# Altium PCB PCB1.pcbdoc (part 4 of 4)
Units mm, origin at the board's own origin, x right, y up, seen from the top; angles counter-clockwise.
Board outline 94.87 x 122.94 mm, 4 copper layers (Top Layer, Inner1, Inner2, Bottom Layer); 129 components, 127 nets, 713 pads, 345 vias.
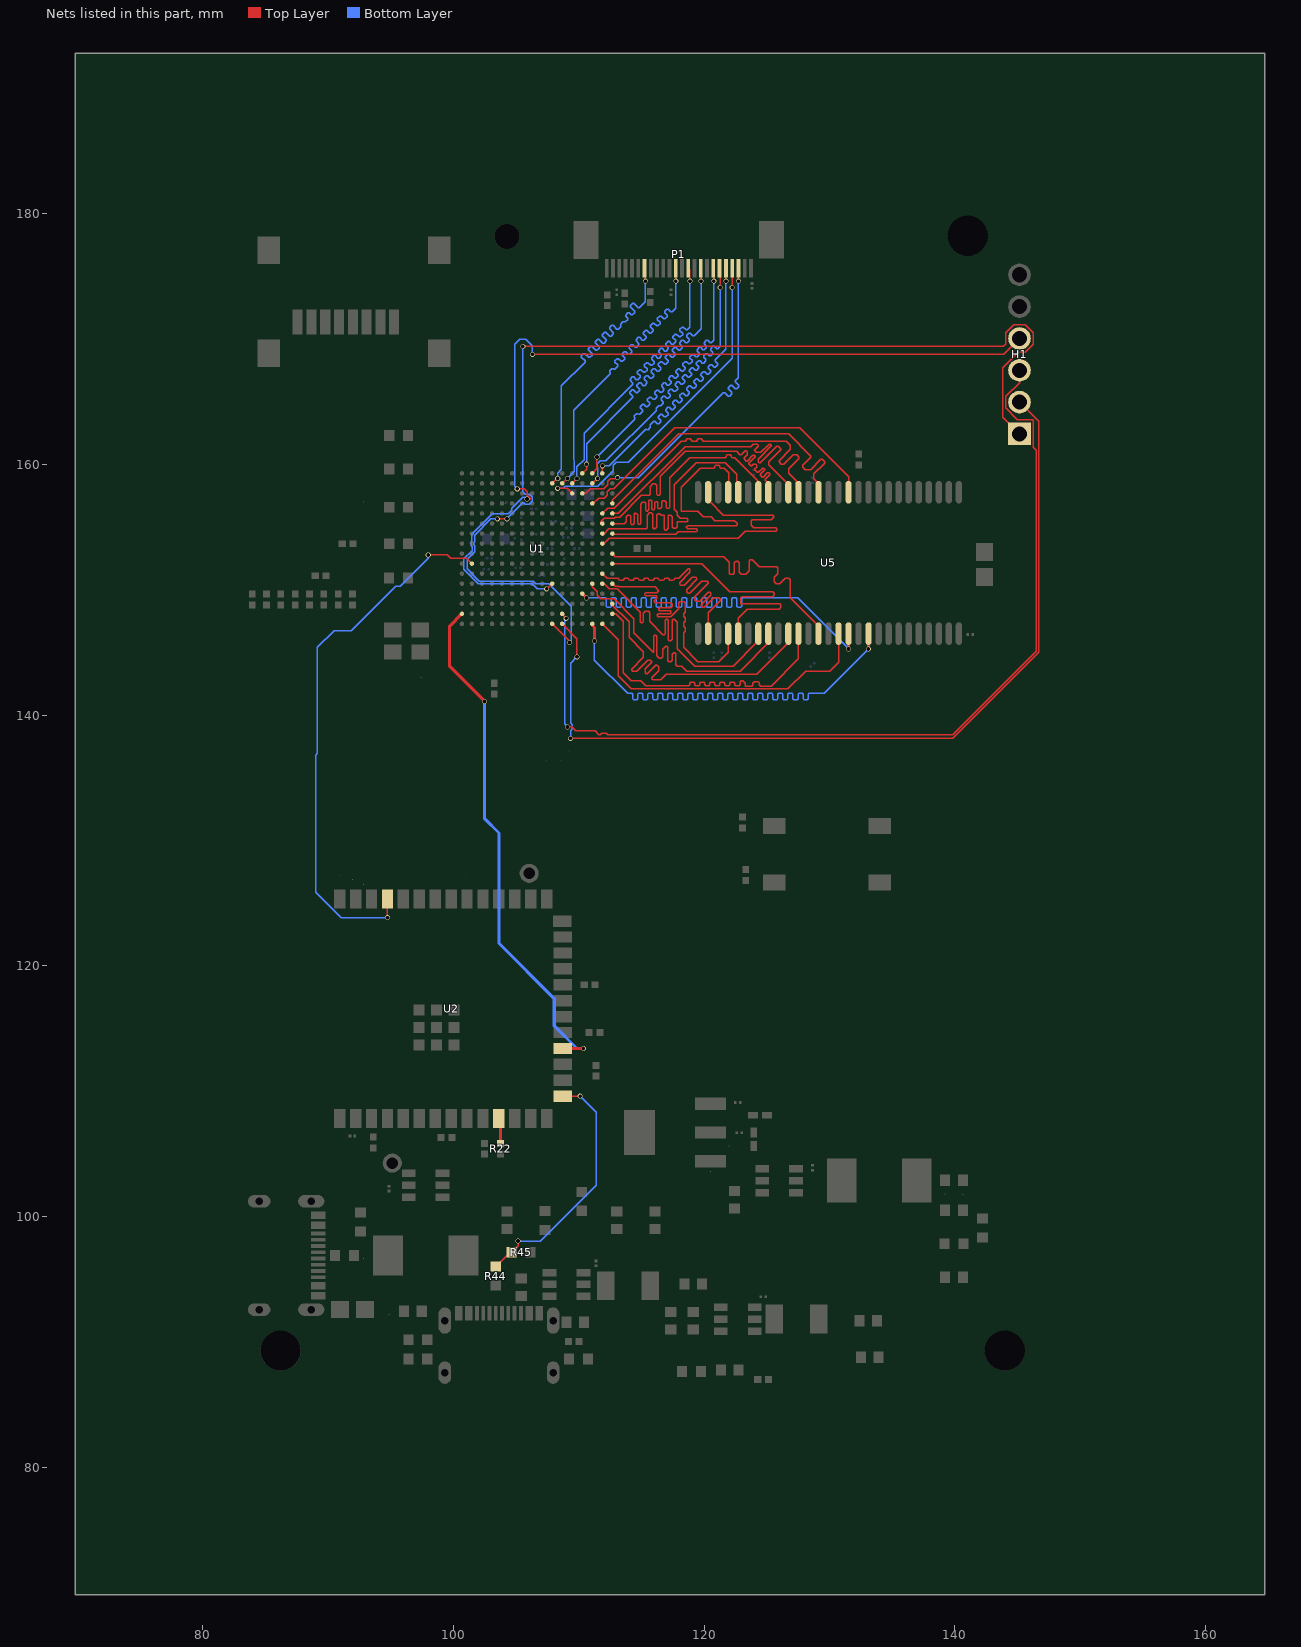
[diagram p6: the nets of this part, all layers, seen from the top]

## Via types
v1: diameter 0.4, hole 0.3, Top Layer to Bottom Layer, 308 vias
v2: diameter 1, hole 0.5, Top Layer to Bottom Layer, 35 vias
v3: diameter 0.5, hole 0.3, Top Layer to Bottom Layer, 2 vias

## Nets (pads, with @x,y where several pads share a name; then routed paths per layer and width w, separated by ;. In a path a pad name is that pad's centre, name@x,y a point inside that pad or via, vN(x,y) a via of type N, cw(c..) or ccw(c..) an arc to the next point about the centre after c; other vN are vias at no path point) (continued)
SD_DQ0: U1.L15 U5.2 | length 25
  Top Layer w0.1: U1.L15@111.88,151.289 112.262,150.907 113.129,150.907 113.2,150.836 113.2,150.82 113.27,150.749 113.529,150.749 113.6,150.82 113.6,150.836 113.67,150.907 113.929,150.907 114,150.836 114,150.82 114.07,150.749 114.329,150.749 114.4,150.82 114.4,150.836 114.47,150.907 114.729,150.907 114.8,150.836 114.8,150.82 114.87,150.749 115.129,150.749 115.2,150.82 115.2,150.836 115.27,150.907 115.529,150.907 115.6,150.836 115.6,150.82 115.67,150.749 115.929,150.749 116,150.82 116,150.836 116.07,150.907 116.329,150.907 116.4,150.836 116.4,150.82 116.47,150.749 116.729,150.749 116.8,150.82 116.8,150.836 116.87,150.907 117.129,150.907 117.2,150.836 117.2,150.82 117.27,150.749 117.529,150.749 117.6,150.82 117.6,150.836 117.67,150.907 117.97,150.907 118.731,151.667 118.843,151.667 118.872,151.638 118.872,151.384 118.049,150.561 118.049,150.429 118.11,150.368 118.411,150.368 119.046,151.003 119.355,151.003 119.426,150.932 119.426,150.832 118.618,150.024 118.618,149.86 118.745,149.733 118.836,149.733 119.795,150.693 120.25,150.693 120.321,150.622 120.321,150.528 119.253,149.46 119.253,149.225 119.38,149.098 119.634,149.098 120.34,149.804 120.452,149.804 120.523,149.733 120.523,149.581 119.761,148.819 119.761,148.717 119.888,148.59 120.015,148.59 120.777,149.352 121.175,149.352 121.295,149.231 121.295,149.131 120.321,148.157 U5.2@120.321,146.631
SD_DQ1: U1.M16 U5.4 | length 25
  Top Layer w0.1: U1.M16@112.68,150.489 112.896,150.273 113.157,150.273 113.195,150.235 116.084,150.235 116.385,149.934 116.214,149.762 115.316,149.762 115.245,149.691 115.245,149.591 115.316,149.521 116.163,149.521 116.205,149.479 116.205,149.34 116.007,149.143 116.007,149.043 116.078,148.972 117.347,148.972 117.454,148.865 117.454,148.696 117.327,148.569 116.459,148.569 116.394,148.504 116.394,148.412 116.459,148.348 117.347,148.348 117.347,148.114 117.33,148.096 116.332,148.096 116.261,148.026 116.261,147.926 116.332,147.855 117.347,147.855 117.983,148.491 117.983,148.971 118.054,149.042 118.42,149.042 118.491,148.971 118.491,148.209 118.364,148.082 118.364,147.878 118.484,147.758 118.484,147.478 118.364,147.358 118.364,147.078 118.484,146.958 118.484,146.678 118.364,146.558 118.364,145.415 119.507,144.272 121.158,144.272 121.921,145.035 U5.4@121.921,146.631
SD_DQ2: U1.K16 U5.5 | length 25.6
  Top Layer w0.1: U1.K16@112.68,152.089 119.818,152.089 122.047,149.86 125.476,149.86 125.603,149.733 125.603,149.606 125.46,149.463 123.028,149.463 122.918,149.352 122.918,148.948 122.978,148.888 126.04,148.888 126.111,148.817 126.111,148.59 125.985,148.464 123.445,148.464 122.704,147.723 122.704,146.902 122.721,146.885 U5.5@122.721,146.631
SD_DQ3: U1.M15 U5.7 | length 24.8
  Top Layer w0.1: U1.M15@111.88,150.489 111.96,150.489 111.974,150.474 112.022,150.474 112.425,150.071 113.073,150.071 114.92,148.224 114.92,147.447 114.99,147.376 115.09,147.376 115.161,147.447 115.161,148.124 115.316,148.279 115.57,148.279 115.67,148.179 115.67,147.474 116.713,146.431 116.84,146.431 116.898,146.489 116.898,147.574 116.969,147.645 117.069,147.645 117.139,147.574 117.139,146.005 117.221,145.923 117.348,145.923 117.472,146.047 117.472,147.574 117.531,147.633 117.614,147.633 117.836,147.411 117.836,145.308 119.253,143.891 122.306,143.891 124.177,145.762 124.177,146.36 124.194,146.377 124.194,146.504 U5.7@124.321,146.631
SD_DQ4: U1.M14 U5.8 | length 25.8
  Top Layer w0.1: U1.M14@111.08,150.489 111.08,150.229 111.462,149.847 111.462,149.567 111.758,149.271 112.838,149.271 114.4,147.709 114.4,146.558 115.958,145 115.99,145.032 115.99,146.304 116.061,146.375 116.161,146.375 116.231,146.304 116.231,144.727 116.432,144.526 116.586,144.526 116.705,144.645 116.705,145.267 116.923,145.486 117.023,145.486 117.094,145.415 117.094,144.372 117.194,144.272 117.348,144.272 117.44,144.364 117.44,144.86 117.558,144.978 117.658,144.978 117.729,144.907 117.729,144.04 117.856,143.913 118.196,143.913 118.599,143.51 122.87,143.51 125.278,145.918 125.278,146.474 U5.8@125.121,146.631
SD_DQ5: U1.P16 U5.10 | length 25.6
  Top Layer w0.1: U1.P16@112.68,148.889 112.68,148.78 114.025,147.435 114.025,146.198 115.159,145.064 115.159,144.61 114.229,143.681 114.229,143.581 114.3,143.51 114.62,143.51 115.509,144.399 115.697,144.399 115.824,144.272 115.824,144.206 115.303,143.686 115.303,143.37 115.374,143.3 115.474,143.3 116.199,144.024 116.368,143.855 116.368,143.533 115.817,142.982 115.817,142.882 115.888,142.811 116.522,142.811 116.967,143.256 124.198,143.256 126.721,145.779 U5.10@126.721,146.631
SD_DQ6: U1.R16 U5.11 | length 25.2
  Top Layer w0.1: U1.R16@112.68,148.089 112.944,148.089 113.538,147.495 113.538,143.383 114.169,142.752 114.931,142.752 115.332,142.351 118.774,142.351 118.844,142.422 118.844,142.55 118.915,142.621 119.174,142.621 119.244,142.55 119.244,142.422 119.315,142.351 119.574,142.351 119.644,142.422 119.644,142.55 119.715,142.621 119.974,142.621 120.044,142.55 120.044,142.422 120.115,142.351 120.374,142.351 120.444,142.422 120.444,142.55 120.515,142.621 120.774,142.621 120.844,142.55 120.844,142.422 120.915,142.351 121.174,142.351 121.244,142.422 121.244,142.55 121.315,142.621 121.574,142.621 121.644,142.55 121.644,142.422 121.715,142.351 121.974,142.351 122.044,142.422 122.044,142.55 122.115,142.621 122.374,142.621 122.444,142.55 122.444,142.422 122.515,142.351 122.792,142.351 122.892,142.451 122.892,142.677 122.963,142.748 123.063,142.748 123.269,142.542 123.269,142.291 123.781,142.291 123.881,142.391 123.881,142.55 124.008,142.677 124.333,142.677 124.404,142.607 124.404,142.421 124.504,142.321 125.335,142.321 127.508,144.494 U5.11@127.508,146.126
SD_DQ7: U1.J16 U5.13 | length 25.2
  Top Layer w0.1: U1.J16@112.68,152.889 112.915,152.654 121.567,152.654 122.003,152.217 122.003,151.315 122.074,151.244 122.315,151.244 122.415,151.344 122.415,152.146 122.552,152.282 122.673,152.282 122.811,152.144 122.811,151.409 122.976,151.244 123.304,151.244 123.587,151.527 123.587,152.289 123.698,152.4 123.841,152.4 124.409,151.832 124.413,151.836 125.786,151.836 125.857,151.765 125.857,151.266 125.603,151.012 125.603,150.638 125.746,150.495 126.043,150.495 126.478,150.931 126.746,150.931 126.875,150.801 126.875,149.367 ; 126.875,149.366 129.121,147.12 U5.13@129.121,146.631
SD_DQ8: U1.D16 U5.42 | length 25.2
  Top Layer w0.1: U1.D16@112.68,156.889 112.68,157.143 117.97,162.433 126.746,162.433 128.524,160.655 128.524,160.574 127.868,159.918 127.868,159.766 128.056,159.578 128.49,159.578 129.313,160.401 129.413,160.401 129.611,160.203 129.611,160.091 129.54,160.02 129.534,160.02 128.757,159.243 128.757,158.877 128.994,158.64 128.994,158.042 U5.42@129.121,157.915
SD_DQ9: U1.E15 U5.44 | length 25
  Top Layer w0.1: U1.E15@111.88,156.089 112.298,156.507 112.838,156.507 118.193,161.862 118.493,161.862 118.563,161.932 118.563,161.981 118.634,162.052 118.893,162.052 118.963,161.981 118.963,161.932 119.034,161.862 119.379,161.862 119.45,161.932 119.45,161.981 119.521,162.052 119.779,162.052 119.85,161.981 119.85,161.932 119.921,161.862 126.555,161.862 126.873,161.544 126.873,161.205 125.984,160.316 125.984,160.208 126.172,160.02 126.365,160.02 127.127,160.782 127.381,160.782 127.55,160.613 127.55,160.471 126.746,159.667 126.746,159.288 127.33,158.704 127.33,158.106 U5.44@127.521,157.915
SD_DQ10: U1.E16 U5.45 | length 25
  Top Layer w0.1: U1.E16@112.68,156.089 113.163,156.089 118.491,161.417 123.708,161.417 123.906,161.615 124.262,161.615 124.333,161.544 124.333,161.458 124,161.125 124.158,160.967 124.531,160.967 125.178,161.615 125.278,161.615 125.349,161.544 125.349,161.477 124.303,160.431 124.303,160.204 124.374,160.133 124.474,160.133 125.807,161.467 125.907,161.467 126.111,161.263 126.111,161.163 125.15,160.202 125.15,159.975 126.373,158.752 126.373,158.747 126.507,158.613 126.507,158.015 126.607,157.915 U5.45@126.721,157.915
SD_DQ11: U1.F15 U5.47 | length 25.1
  Top Layer w0.1: U1.F15@111.88,155.289 111.753,155.416 111.753,155.441 112.019,155.707 112.838,155.707 112.929,155.798 113.253,155.798 114.991,157.536 115.626,157.536 115.697,157.607 115.697,158.242 115.9,158.445 116.105,158.445 116.205,158.345 116.205,157.607 116.276,157.536 116.425,157.536 116.496,157.607 116.496,159.041 118.491,161.036 122.598,161.036 122.858,160.776 122.943,160.776 123.273,161.107 123.373,161.107 123.444,161.036 123.444,160.782 123.19,160.528 123.19,160.444 123.376,160.259 123.429,160.259 123.896,160.726 124.008,160.726 124.079,160.655 124.079,160.61 123.571,160.102 123.571,160.063 123.771,159.864 123.927,160.02 124.143,160.02 124.206,159.957 124.206,159.797 124.048,159.639 124.048,159.586 124.249,159.385 124.333,159.385 124.658,159.71 124.77,159.71 124.841,159.639 124.841,159.59 124.46,159.209 124.46,159.174 124.655,158.979 124.702,158.979 125.051,159.329 125.151,159.329 125.222,159.258 125.222,159.16 124.884,158.822 124.884,158.75 125.121,158.513 U5.47@125.121,157.915
SD_DQ12: U1.F16 U5.48 | length 25.1
  Top Layer w0.1: U1.F16@112.68,155.289 113.633,155.289 113.792,155.448 113.792,155.829 113.919,155.956 114.086,155.956 114.129,155.912 114.129,155.265 114.2,155.194 114.3,155.194 114.408,155.302 114.408,156.064 114.466,156.122 114.554,156.122 114.689,155.987 114.689,155.325 114.764,155.25 114.864,155.25 114.935,155.321 114.935,156.845 115.062,156.972 115.248,156.972 115.329,156.892 115.329,156.337 115.399,156.266 115.468,156.266 115.57,156.369 115.57,157.094 115.633,157.157 115.766,157.157 115.837,157.086 115.837,156.464 115.907,156.393 116.007,156.393 116.078,156.464 116.078,156.972 116.142,157.036 116.268,157.036 116.303,157.001 116.303,156.52 116.374,156.449 116.474,156.449 116.615,156.591 116.615,157.001 116.713,157.099 116.84,157.099 116.967,156.972 116.967,156.591 117.038,156.52 117.206,156.52 117.277,156.591 117.277,158.933 118.872,160.528 121.681,160.528 121.751,160.599 121.751,160.711 121.822,160.782 122.081,160.782 122.151,160.711 122.151,160.599 122.222,160.528 122.428,160.528 124.263,158.693 124.263,158.015 124.321,157.957 U5.48@124.321,157.915
SD_DQ13: U1.G15 U5.50 | length 25.1
  Top Layer w0.1: U1.G15@111.88,154.489 112.021,154.489 112.403,154.871 115.374,154.871 115.443,154.94 115.443,155.956 115.626,156.139 115.768,156.139 115.895,156.012 115.895,154.94 115.965,154.869 116.065,154.869 116.205,155.009 116.205,155.956 116.332,156.083 116.459,156.083 116.586,155.956 116.802,155.956 116.802,154.813 116.873,154.742 116.973,154.742 117.132,154.902 117.132,155.899 117.189,155.956 117.348,155.956 117.475,155.829 117.475,155.013 117.575,154.913 117.756,154.913 117.856,155.013 117.856,155.406 117.898,155.448 118.618,155.448 118.689,155.519 118.689,155.619 118.61,155.697 118.115,155.697 117.856,155.956 117.856,156.197 117.614,156.44 117.614,158.387 119.374,160.147 121.666,160.147 122.603,159.21 122.603,158.034 U5.50@122.721,157.915
SD_DQ14: U1.G16 U5.51 | length 25
  Top Layer w0.1: U1.G16@112.68,154.489 112.743,154.425 117.722,154.425 117.916,154.619 119.38,154.619 119.451,154.69 119.451,154.79 119.38,154.86 118.698,154.86 118.585,154.973 118.585,155.034 118.68,155.129 122.555,155.129 122.626,155.199 122.626,155.299 122.406,155.519 120.86,155.519 120.55,155.829 119.926,155.829 119.507,156.248 118.157,156.248 118.157,158.162 119.697,159.702 120.761,159.702 120.832,159.773 120.832,159.847 120.902,159.918 121.161,159.918 121.232,159.847 121.232,159.773 121.303,159.702 121.602,159.702 121.967,159.338 121.967,158.25 U5.51@121.985,158.233
SD_DQ15: U1.H15 U5.53 | length 25.3
  Top Layer w0.1: U1.H15@111.88,153.689 112.007,153.689 112.425,154.107 122.711,154.107 123.268,154.664 125.696,154.664 125.801,154.769 125.801,154.869 125.73,154.94 123.952,154.94 123.754,155.138 123.754,155.504 123.825,155.575 125.336,155.575 125.547,155.785 125.547,155.885 125.476,155.956 121.539,155.956 120.448,157.047 U5.53@120.448,157.788
SD_DQM0: U1.T15 U5.15 | length 25.8
  Top Layer w0.1: U1.T15@111.88,147.289 113.157,146.012 113.157,143.129 114.195,142.091 126.69,142.091 128.109,143.51 130.008,143.51 130.721,144.223 U5.15@130.721,146.504
SD_DQM1: U1.D14 U5.39 | length 25.9
  Top Layer w0.1: U1.D14@111.08,156.889 111.169,156.889 111.587,157.307 112.038,157.307 112.262,157.531 112.262,157.811 112.522,158.071 112.802,158.071 117.672,162.941 127.619,162.941 131.53,159.031 131.53,158.042 U5.39@131.403,157.915
SD_RAS_N: U1.T14 U5.18 | length 43.8
  Top Layer w0.254: U1.T14@111.125,147.123 111.252,146.996 v1(111.252,145.923) ; v1(133.096,145.288) 133.121,145.313 U5.18@133.121,146.504
  Bottom Layer w0.1: v1(111.252,145.923) 111.252,144.399 113.919,141.732 114.219,141.732 114.29,141.661 114.29,141.295 114.36,141.224 114.619,141.224 114.69,141.295 114.69,141.661 114.76,141.732 115.019,141.732 115.09,141.661 115.09,141.295 115.16,141.224 115.419,141.224 115.49,141.295 115.49,141.661 115.56,141.732 115.819,141.732 115.89,141.661 115.89,141.295 115.96,141.224 116.219,141.224 116.29,141.295 116.29,141.661 116.36,141.732 116.619,141.732 116.69,141.661 116.69,141.295 116.76,141.224 117.019,141.224 117.09,141.295 117.09,141.661 117.16,141.732 117.419,141.732 117.49,141.661 117.49,141.295 117.56,141.224 117.819,141.224 117.89,141.295 117.89,141.661 117.96,141.732 118.219,141.732 118.29,141.661 118.29,141.295 118.36,141.224 118.619,141.224 118.69,141.295 118.69,141.661 118.76,141.732 119.019,141.732 119.09,141.661 119.09,141.295 119.16,141.224 119.419,141.224 119.49,141.295 119.49,141.661 119.56,141.732 119.819,141.732 119.89,141.661 119.89,141.295 119.96,141.224 120.219,141.224 120.29,141.295 120.29,141.661 120.36,141.732 120.619,141.732 120.69,141.661 120.69,141.295 120.76,141.224 121.019,141.224 121.09,141.295 121.09,141.661 121.16,141.732 121.419,141.732 121.49,141.661 121.49,141.295 121.56,141.224 121.819,141.224 121.89,141.295 121.89,141.661 121.96,141.732 122.219,141.732 122.29,141.661 122.29,141.295 122.36,141.224 122.619,141.224 122.69,141.295 122.69,141.661 122.76,141.732 123.019,141.732 123.09,141.661 123.09,141.295 123.16,141.224 123.419,141.224 123.49,141.295 123.49,141.661 123.56,141.732 123.819,141.732 123.89,141.661 123.89,141.295 123.96,141.224 124.219,141.224 124.29,141.295 124.29,141.661 124.36,141.732 124.619,141.732 124.69,141.661 124.69,141.295 124.76,141.224 125.019,141.224 125.09,141.295 125.09,141.661 125.16,141.732 125.419,141.732 125.49,141.661 125.49,141.295 125.56,141.224 125.819,141.224 125.89,141.295 125.89,141.661 125.96,141.732 126.219,141.732 126.29,141.661 126.29,141.295 126.36,141.224 126.619,141.224 126.69,141.295 126.69,141.661 126.76,141.732 127.019,141.732 127.09,141.661 127.09,141.295 127.16,141.224 127.419,141.224 127.49,141.295 127.49,141.661 127.56,141.732 127.819,141.732 127.89,141.661 127.89,141.295 127.96,141.224 128.219,141.224 128.29,141.295 128.29,141.661 128.36,141.732 129.588,141.732 133.096,145.24 v1(133.096,145.288)
SD_WE_N: U1.N13 U5.16 | length 43.3
  Top Layer w0.254: U1.N13@110.28,149.689 v1(110.617,149.352) ; v1(131.521,145.288) U5.16@131.521,146.504
  Bottom Layer w0.1: v1(110.617,149.352) 112.125,149.352 112.196,149.281 112.196,148.661 112.267,148.59 112.525,148.59 112.596,148.661 112.596,149.281 112.667,149.352 112.925,149.352 112.996,149.281 112.996,148.661 113.067,148.59 113.325,148.59 113.396,148.661 113.396,149.281 113.467,149.352 113.725,149.352 113.796,149.281 113.796,148.661 113.867,148.59 114.125,148.59 114.196,148.661 114.196,149.281 114.267,149.352 114.525,149.352 114.596,149.281 114.596,148.661 114.667,148.59 114.925,148.59 114.996,148.661 114.996,149.281 115.067,149.352 115.325,149.352 115.396,149.281 115.396,148.661 115.467,148.59 115.725,148.59 115.796,148.661 115.796,149.281 115.867,149.352 116.125,149.352 116.196,149.281 116.196,148.661 116.267,148.59 116.525,148.59 116.596,148.661 116.596,149.281 116.667,149.352 116.925,149.352 116.996,149.281 116.996,148.661 117.067,148.59 117.325,148.59 117.396,148.661 117.396,149.281 117.467,149.352 117.725,149.352 117.796,149.281 117.796,148.661 117.867,148.59 118.125,148.59 118.196,148.661 118.196,149.281 118.267,149.352 118.525,149.352 118.596,149.281 118.596,148.661 118.667,148.59 118.925,148.59 118.996,148.661 118.996,149.281 119.067,149.352 119.325,149.352 119.396,149.281 119.396,148.661 119.467,148.59 119.725,148.59 119.796,148.661 119.796,149.281 119.867,149.352 120.125,149.352 120.196,149.281 120.196,148.661 120.267,148.59 120.525,148.59 120.596,148.661 120.596,149.281 120.667,149.352 120.925,149.352 120.996,149.281 120.996,148.661 121.067,148.59 121.325,148.59 121.396,148.661 121.396,149.281 121.467,149.352 121.725,149.352 121.796,149.281 121.796,148.661 121.867,148.59 122.125,148.59 122.196,148.661 122.196,149.281 122.267,149.352 122.525,149.352 122.596,149.281 122.596,148.661 122.667,148.59 122.925,148.59 122.996,148.661 122.996,149.281 123.067,149.352 127.457,149.352 v1(131.521,145.288)
SDA: R22.1 U2.11 | length 1.9
  Top Layer w0.254: R22.1@103.754,105.918 U2.11@103.754,107.836
SSPI_CS_N: U1.R1 U2.18 | length 41.3
  Top Layer w0.254: U1.R1@100.68,148.089 99.695,147.104 99.695,143.891 v1(102.489,141.097) ; U2.18@108.844,113.411 v1(110.363,113.411)
  Bottom Layer w0.254: v1(102.489,141.097) 102.489,131.743 103.632,130.6 103.632,121.793 108.05,117.375 108.05,115.216 109.855,113.411 v1(110.363,113.411)
TCK: H1.1 U1.T10 | length 88.4
  Top Layer w0.1: v1(103.501,155.661) 103.712,155.661 103.722,155.671 104.038,155.671 104.048,155.661 104.226,155.661 v1@104.267,155.702 ; v1(105.537,169.418) 143.875,169.418 144.059,169.602 144.059,170.509 144.705,171.155 145.617,171.155 146.263,170.509 146.263,169.597 145.617,168.951 145.041,168.951 143.808,167.719 143.808,163.786 H1.1@145.161,162.433 ; U1.T10@107.88,147.289 109.264,145.905 v1(109.264,145.796)
  Bottom Layer w0.1: v1(103.501,155.661) 102.985,155.661 101.682,154.358 101.682,153.802 101.633,153.752 101.633,153.6 101.694,153.538 101.694,153.04 101.092,152.438 101.092,151.667 102.064,150.695 106.363,150.695 106.576,150.481 107.609,150.481 109.395,148.695 109.395,145.927 v1(109.264,145.796) ; v1(104.267,155.661) 105.537,156.931 105.622,156.931 105.714,156.839 106.047,156.839 106.282,157.075 106.282,157.408 106.047,157.643 105.714,157.643 105.537,157.82 v1(105.537,169.418)
TDI: H1.3 U1.R11 | length 74.5
  Top Layer w0.1: U1.R11@108.68,148.089 108.68,148.041 v1(108.993,147.728) ; v1(109.093,139.065) 109.421,139.065 109.748,138.738 111.298,138.738 111.606,138.43 111.72,138.43 111.847,138.557 112.181,138.557 112.308,138.43 139.827,138.43 146.485,145.088 146.485,161.153 146.272,161.366 146.272,163.579 144.996,163.579 144.059,164.517 144.059,165.429 145.161,166.531 H1.3@145.161,167.513
  Bottom Layer w0.1: v1(108.993,147.728) 108.862,147.597 108.862,139.296 v1(109.093,139.065)
TDO: H1.4 U1.M10 | length 72.1
  Top Layer w0.1: v1(105.092,158.054) 105.304,158.054 105.322,158.071 105.638,158.071 105.898,157.811 105.898,157.531 106.122,157.307 106.122,157.271 106.092,157.241 v1(105.88,157.241) ; v1(106.299,168.783) 143.891,168.783 H1.4@145.161,170.053 ; v1(107.442,150.079) 107.47,150.079 U1.M10@107.88,150.489
  Bottom Layer w0.1: v1(105.092,158.054) 104.881,158.265 104.881,169.601 105.281,170.001 105.762,170.001 106.299,169.464 v1(106.299,168.783) ; v1(105.88,157.241) 105.753,157.368 105.524,157.368 104.669,156.514 104.669,156.357 104.375,156.063 103.104,156.063 101.482,154.441 101.482,153.884 101.433,153.835 101.433,153.517 101.494,153.456 101.494,153.122 100.838,152.466 100.838,151.638 101.981,150.495 106.28,150.495 106.695,150.079 v1(107.442,150.079)
TMS: H1.2 U1.T11 | length 70.7
  Top Layer w0.1: U1.T11@108.68,147.289 109.855,146.114 v1(109.855,144.653) ; v1(109.347,138.155) 139.835,138.155 146.685,145.005 146.685,163.449 H1.2@145.161,164.973
  Bottom Layer w0.1: v1(109.347,138.155) 109.347,138.75 109.495,138.898 109.495,139.232 109.347,139.38 109.347,144.145 v1(109.855,144.653)
TX: U1.K2 U2.37 | length 43.6
  Top Layer w0.1: v1@94.737,123.825 U2.37@94.737,125.336 ; v1@97.917,152.781 99.507,152.781 99.782,152.506 101.061,152.506 ; 101.062,152.507 U1.K2@101.48,152.089
  Bottom Layer w0.1: v1(94.737,123.846) 91.038,123.846 89.004,125.88 89.004,136.809 89.154,136.959 89.154,145.415 90.478,146.739 91.85,146.739 95.385,150.274 95.753,150.274 97.992,152.513 v1(97.992,152.781)
USB_VBUS: R44.1 R45.2 U2.15 | length 19.9
  Top Layer w0.1: R44.1@103.378,96.003 104.53,97.155 R45.2@104.657,97.155 105.156,97.654 v1(105.156,98.044) ; U2.15@108.717,109.601 v1(110.109,109.601)
  Bottom Layer w0.1: v1(105.156,98.044) 106.934,98.044 111.379,102.489 111.379,108.331 v1(110.109,109.601)
VSYNC: P1.7 U1.B10 | length 27.1
  Top Layer w0.1: U1.B10@107.88,158.489 108.276,158.885 v1(108.323,158.885) ; P1.7@115.237,175.655 115.316,175.577 v1(115.316,174.625)
  Bottom Layer w0.1: v1(108.323,158.885) 108.323,159.317 108.606,159.599 108.606,166.264 110.501,168.159 110.501,168.259 110.192,168.568 110.192,168.668 110.375,168.851 110.475,168.851 110.784,168.542 110.884,168.542 111.067,168.725 111.067,168.825 110.758,169.134 110.758,169.234 110.94,169.417 111.04,169.417 111.35,169.108 111.45,169.108 111.632,169.29 111.632,169.39 111.323,169.7 111.323,169.8 111.506,169.982 111.606,169.982 111.915,169.673 112.015,169.673 112.198,169.856 112.198,169.956 111.889,170.265 111.889,170.365 112.072,170.548 112.172,170.548 112.481,170.239 112.581,170.239 112.764,170.422 112.764,170.522 112.455,170.831 112.455,170.931 112.638,171.114 112.738,171.114 113.047,170.805 113.147,170.805 113.333,170.991 113.333,171.184 113.52,171.37 113.712,171.37 113.895,171.553 113.895,171.653 113.729,171.819 113.729,171.919 113.912,172.102 114.012,172.102 114.178,171.936 114.278,171.936 114.461,172.119 114.461,172.219 114.116,172.563 114.116,172.663 114.299,172.846 114.399,172.846 114.744,172.502 114.844,172.502 115.316,172.974 v1(115.316,174.625)
Y2: P1.19 U1.B14 | length 27
  Top Layer w0.1: U1.B14@111.08,158.489 111.468,158.877 v1(111.506,158.877) ; P1.19@121.237,175.655 121.285,175.607 v1(121.285,174.117)
  Bottom Layer w0.1: v1(111.506,158.877) 111.506,159.705 111.485,159.726 111.485,160.06 111.72,160.295 112.162,160.295 116.166,164.299 116.166,164.465 116.367,164.665 116.532,164.665 116.748,164.881 116.748,164.981 116.56,165.169 116.56,165.269 116.742,165.451 116.842,165.451 117.03,165.263 117.13,165.263 117.313,165.446 117.313,165.546 117.125,165.734 117.125,165.834 117.308,166.017 117.408,166.017 117.596,165.829 117.696,165.829 117.879,166.012 117.879,166.112 117.691,166.3 117.691,166.4 117.874,166.583 117.974,166.583 118.162,166.395 118.262,166.395 118.445,166.578 118.445,166.678 118.257,166.866 118.257,166.966 118.44,167.148 118.54,167.148 118.728,166.961 118.828,166.961 119.01,167.143 119.01,167.243 118.822,167.431 118.822,167.531 119.005,167.714 119.105,167.714 119.293,167.526 119.393,167.526 119.576,167.709 119.576,167.809 119.388,167.997 119.388,168.097 119.571,168.28 119.671,168.28 119.859,168.092 119.959,168.092 120.142,168.275 120.142,168.375 119.954,168.563 119.954,168.663 120.137,168.846 120.237,168.846 120.425,168.658 120.525,168.658 120.707,168.84 120.707,168.94 120.519,169.128 120.519,169.228 120.702,169.411 120.802,169.411 120.99,169.223 121.09,169.223 121.285,169.418 v1(121.285,174.117)
Y3: P1.21 U1.C12 | length 27
  Top Layer w0.1: v1(108.317,158.1) 109.069,158.1 U1.C12@109.48,157.689 ; v1(122.239,174.117) P1.21@122.239,175.652
  Bottom Layer w0.1: v1(108.317,158.1) 108.766,158.1 108.925,158.259 111.523,158.259 112.755,159.491 112.755,159.933 112.99,160.168 113.94,160.168 122.239,168.467 v1(122.239,174.117)
Y4: P1.22 U1.C13 | length 27
  Top Layer w0.1: U1.C13@110.28,157.689 110.54,157.689 110.922,158.071 112.002,158.071 112.298,158.367 112.298,158.647 112.522,158.871 113.014,158.871 v1(113.089,158.945) ; v1(122.739,174.625) P1.22@122.739,175.652
  Bottom Layer w0.1: v1(113.089,158.945) 114.749,158.945 121.544,165.74 121.644,165.74 121.925,165.459 122.025,165.459 122.208,165.642 122.208,165.742 121.927,166.023 121.927,166.123 122.11,166.306 122.21,166.306 122.491,166.025 122.591,166.025 122.774,166.208 122.774,166.308 122.493,166.589 122.493,166.689 122.739,166.935 v1(122.739,174.625)
Y5: P1.20 U1.A15 | length 27
  Top Layer w0.1: U1.A15@111.88,159.289 111.887,159.296 v1(111.887,159.893) ; v1(121.739,174.625) P1.20@121.739,175.652
  Bottom Layer w0.1: v1(111.887,159.893) 112.433,159.893 115.33,162.791 115.43,162.791 115.438,162.782 115.538,162.782 115.721,162.965 115.721,163.065 115.713,163.074 115.713,163.174 115.973,163.434 116.073,163.434 116.272,163.235 116.372,163.235 116.555,163.418 116.555,163.518 116.356,163.717 116.356,163.817 116.539,163.999 116.639,163.999 116.838,163.801 116.938,163.801 117.121,163.984 117.121,164.084 116.922,164.282 116.922,164.382 117.105,164.565 117.205,164.565 117.403,164.366 117.503,164.366 117.686,164.549 117.686,164.649 117.488,164.848 117.488,164.948 117.67,165.131 117.77,165.131 117.969,164.932 118.069,164.932 118.252,165.115 118.252,165.215 118.053,165.414 118.053,165.514 118.236,165.696 118.336,165.696 118.535,165.498 118.635,165.498 118.818,165.681 118.818,165.781 118.619,165.979 118.619,166.079 118.802,166.262 118.902,166.262 119.1,166.063 119.2,166.063 119.383,166.246 119.383,166.346 119.185,166.545 119.185,166.645 119.367,166.828 119.467,166.828 119.666,166.629 119.766,166.629 119.949,166.812 119.949,166.912 119.75,167.111 119.75,167.211 119.933,167.393 120.033,167.393 120.232,167.195 120.332,167.195 120.515,167.378 120.515,167.478 120.316,167.676 120.316,167.776 120.499,167.959 120.599,167.959 120.797,167.76 120.897,167.76 121.08,167.943 121.08,168.043 120.882,168.242 120.882,168.342 121.739,169.199 v1(121.739,174.625)
Y6: P1.18 U1.A14 | length 27.1
  Top Layer w0.1: U1.A14@111.08,159.289 111.445,159.654 v1(111.445,160.589) ; P1.18@120.737,175.655 120.777,175.615 v1(120.777,174.625)
  Bottom Layer w0.1: v1(111.445,160.589) 114.484,163.627 114.484,163.727 114.438,163.772 114.438,163.872 114.621,164.055 114.721,164.055 114.767,164.01 114.867,164.01 115.096,164.239 115.096,164.339 114.91,164.524 114.91,164.624 115.093,164.807 115.193,164.807 115.378,164.621 115.478,164.621 115.661,164.804 115.661,164.904 115.476,165.09 115.476,165.19 115.659,165.372 115.759,165.372 115.944,165.187 116.044,165.187 116.227,165.37 116.227,165.47 116.042,165.655 116.042,165.755 116.224,165.938 116.324,165.938 116.51,165.753 116.61,165.753 116.793,165.936 116.793,166.036 116.607,166.221 116.607,166.321 116.79,166.504 116.89,166.504 117.075,166.318 117.175,166.318 117.358,166.501 117.358,166.601 117.173,166.787 117.173,166.887 117.356,167.07 117.456,167.07 117.641,166.884 117.741,166.884 117.924,167.067 117.924,167.167 117.739,167.352 117.739,167.452 117.921,167.635 118.021,167.635 118.207,167.45 118.307,167.45 118.49,167.633 118.49,167.733 118.304,167.918 118.304,168.018 118.487,168.201 118.587,168.201 118.772,168.016 118.872,168.016 119.055,168.198 119.055,168.298 118.87,168.484 118.87,168.584 119.053,168.767 119.153,168.767 119.338,168.581 119.438,168.581 119.621,168.764 119.621,168.864 119.436,169.049 119.436,169.149 119.619,169.332 119.719,169.332 119.904,169.147 120.004,169.147 120.187,169.33 120.187,169.43 120.001,169.615 120.001,169.715 120.184,169.898 120.284,169.898 120.47,169.713 120.57,169.713 120.777,169.92 v1(120.777,174.625)
Y7: P1.16 U1.A13 | length 26.9
  Top Layer w0.1: U1.A13@110.28,159.289 110.617,159.626 v1(110.617,160.02) ; P1.16@119.737,175.654 119.761,175.63 v1(119.761,174.625)
  Bottom Layer w0.1: v1(110.617,160.02) 110.617,161.671 114.295,165.349 114.295,165.449 114.078,165.667 114.078,165.767 114.26,165.949 114.36,165.949 114.578,165.732 114.678,165.732 114.861,165.915 114.861,166.015 114.643,166.232 114.643,166.332 114.826,166.515 114.926,166.515 115.144,166.298 115.244,166.298 115.426,166.48 115.426,166.58 115.209,166.798 115.209,166.898 115.392,167.081 115.492,167.081 115.709,166.863 115.809,166.863 115.992,167.046 115.992,167.146 115.775,167.364 115.775,167.464 115.957,167.646 116.057,167.646 116.275,167.429 116.375,167.429 116.558,167.612 116.558,167.712 116.34,167.929 116.34,168.029 116.523,168.212 116.623,168.212 116.841,167.995 116.941,167.995 117.123,168.177 117.123,168.277 116.906,168.495 116.906,168.595 117.089,168.778 117.189,168.778 117.406,168.56 117.506,168.56 117.689,168.743 117.689,168.843 117.472,169.061 117.472,169.161 117.654,169.343 117.754,169.343 117.972,169.126 118.072,169.126 118.255,169.309 118.255,169.409 118.037,169.626 118.037,169.726 118.22,169.909 118.32,169.909 118.538,169.692 118.638,169.692 118.82,169.874 118.82,169.974 118.603,170.192 118.603,170.292 118.786,170.475 118.886,170.475 119.103,170.257 119.203,170.257 119.761,170.815 v1(119.761,174.625)
Y8: P1.14 U1.B12 | length 27
  Top Layer w0.1: U1.B12@109.48,158.489 109.855,158.864 v1(109.855,158.877) ; P1.14@118.738,175.655 118.868,175.524 v1(118.868,174.621)
  Bottom Layer w0.1: v1(109.855,158.877) 109.855,159.827 110.417,160.389 110.417,162.487 114.315,166.385 114.315,166.485 114.097,166.702 114.097,166.802 114.28,166.985 114.38,166.985 114.598,166.768 114.698,166.768 114.891,166.961 114.891,167.061 114.674,167.279 114.674,167.379 114.857,167.562 114.957,167.562 115.174,167.344 115.274,167.344 115.457,167.527 115.457,167.627 115.239,167.844 115.239,167.944 115.422,168.127 115.522,168.127 115.74,167.91 115.84,167.91 116.023,168.093 116.023,168.193 115.805,168.41 115.805,168.51 115.988,168.693 116.088,168.693 116.305,168.475 116.405,168.475 116.588,168.658 116.588,168.758 116.371,168.976 116.371,169.076 116.554,169.259 116.654,169.259 116.871,169.041 116.971,169.041 117.154,169.224 117.154,169.324 116.936,169.541 116.936,169.641 117.119,169.824 117.219,169.824 117.437,169.607 117.537,169.607 117.72,169.79 117.72,169.89 117.502,170.107 117.502,170.207 117.685,170.39 117.785,170.39 118.003,170.173 118.103,170.173 118.285,170.355 118.285,170.455 118.068,170.673 118.068,170.773 118.251,170.956 118.351,170.956 118.568,170.738 118.668,170.738 118.868,170.938 v1(118.868,174.621)
Y9: P1.12 U1.B11 | length 27
  Top Layer w0.1: U1.B11@108.68,158.489 109.068,158.877 v1(109.093,158.877) ; v1(117.738,174.625) P1.12@117.738,175.655
  Bottom Layer w0.1: v1(109.093,158.877) 109.655,159.439 109.655,160.286 109.58,160.361 109.58,164.317 112.492,167.229 112.492,167.329 112.465,167.356 112.465,167.456 112.648,167.639 112.748,167.639 112.775,167.612 112.875,167.612 113.101,167.838 113.101,167.938 112.884,168.156 112.884,168.256 113.067,168.439 113.167,168.439 113.384,168.221 113.484,168.221 113.667,168.404 113.667,168.504 113.449,168.721 113.449,168.821 113.632,169.004 113.732,169.004 113.95,168.787 114.05,168.787 114.233,168.97 114.233,169.07 114.015,169.287 114.015,169.387 114.198,169.57 114.298,169.57 114.516,169.353 114.616,169.353 114.798,169.535 114.798,169.635 114.581,169.853 114.581,169.953 114.764,170.136 114.864,170.136 115.081,169.918 115.181,169.918 115.364,170.101 115.364,170.201 115.147,170.419 115.147,170.519 115.329,170.701 115.429,170.701 115.647,170.484 115.747,170.484 115.93,170.667 115.93,170.767 115.712,170.984 115.712,171.084 115.895,171.267 115.995,171.267 116.213,171.05 116.313,171.05 116.495,171.232 116.495,171.332 116.278,171.55 116.278,171.65 116.461,171.833 116.561,171.833 116.778,171.615 116.878,171.615 117.061,171.798 117.061,171.898 116.844,172.116 116.844,172.216 117.026,172.398 117.126,172.398 117.344,172.181 117.444,172.181 117.738,172.475 v1(117.738,174.625)
pads on no net: P1.1 P1.10 SCREW1.1 SCREW2.1 SCREW3.1 SCREW4.1 U1.A9 U1.B3 U1.B8 U1.B13 U1.B15 U1.B16 U1.C1 U1.C2 U1.C3 U1.C4 U1.C5 U1.C6 U1.C9 U1.C10 U1.C11 U1.C14 U1.C15 U1.C16 U1.D1 U1.D3 U1.D4 U1.D5 U1.D6 U1.D7 U1.D8 U1.D9 U1.D10 U1.D11 U1.D12 U1.D13 U1.E3 U1.E4 U1.E5 U1.E6 U1.E7 U1.E8 U1.E9 U1.E10 U1.E11 U1.E12 U1.E13 U1.E14 U1.F3 U1.F4 U1.F5 U1.F12 U1.F13 U1.F14 U1.G3 U1.G4 U1.G5 U1.G12 U1.G13 U1.G14 U1.H2 U1.H3 U1.H4 U1.H5 U1.H12 U1.H13 U1.H14 U1.J3 U1.J4 U1.J5 U1.J12 U1.J13 U1.K3 U1.K4 U1.K5 U1.K13 U1.K14 U1.K15 U1.L1 U1.L2 U1.L3 U1.L4 U1.L5 U1.L13 U1.L14 U1.L16 U1.M2 U1.M3 U1.M4 U1.M5 U1.M6 U1.M7 U1.M9 U1.M11 U1.M12 U1.M13 U1.N1 U1.N3 U1.N4 U1.N5 U1.N6 U1.N7 U1.N8 U1.N9 U1.N11 U1.N12 U1.N14 U1.N16 U1.P1 U1.P2 U1.P3 U1.P4 U1.P5 U1.P6 U1.P7 U1.P8 U1.P11 U1.P12 U1.P13 U1.P14 U1.P15 U1.R2 U1.R3 U1.R4 U1.R5 U1.R6 U1.R7 U1.R8 U1.R12 U1.R14 U1.T13 U2.4 U2.16 U2.26 U2.28 U2.29 U2.30 U2.32 U2.33 U2.34 U2.35 U2.38 U2.39 U5.40 U8.4 USB1.A6 USB1.A7 USB1.A8 USB1.B6 USB1.B7 USB1.B8 USB2.A8 USB2.B6 USB2.B7 USB2.B8
copper on no net: | length 14.9
  Top Layer w0.1: 91.948,126.873 92.197,126.624 92.197,125.336 ; 92.837,126.492 93.467,125.862 93.467,125.336 ; 94.737,107.836 94.966,107.607 v1(94.966,106.202) ; 103.627,125.336 103.627,125.971 105.164,127.508 105.791,127.508 106.045,127.254 ; v1(108.332,148.589) 108.381,148.59 108.68,148.889
  Top Layer w0.254: v1(99.822,148.921) 100.648,148.921 100.68,148.889 ; v1(101.077,149.334) 101.48,148.93 101.48,148.889 ; v1(101.875,149.246) 101.875,149.284 102.28,149.689 ; v1(102.632,148.489) 102.68,148.489 103.08,148.889 ; v1(102.743,149.352) 103.08,149.689
  Bottom Layer w0.1: v1(94.966,106.202) 95.123,106.045 95.123,104.267 ; v1(108.332,148.589) 108.712,148.209 108.712,148.082

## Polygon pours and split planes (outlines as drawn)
+3V3 on Inner2 (solid, remove dead copper): 76.2,185.674 158.369,185.674 158.369,76.2 76.2,76.2
GND on Inner1 (solid, remove dead copper): 77.724,186.436 152.781,186.436 152.781,82.296 77.724,82.296

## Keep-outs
Board Outline Layer:
  lines w0.254: 83.058,86.229 147.058,86.229 147.058,181.229 83.058,181.229 83.058,86.229

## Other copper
Top Layer:
  drawing of 759 lines, arcs and shapes, not listed
Inner2:
  region net +2V5: 113.901,150.822 114.608,151.529 ccw(c146.437,183.357) 115.687,150.486 114.944,149.743 ccw(c82.073,118.993)
  region net +1V8: 109.353,157.325 113.339,157.248 118.08,154.57 cw(c123.53,160.02) 115.924,158.777 113.599,157.853 110.581,157.825
  region net +1V8: 112.657,157.325 112.657,157.825 ccw(c112.657,162.875) 113.657,157.925 113.657,157.225 ccw(c112.657,152.275)
  region net +1V8: 111.979,157.325 111.979,157.825 ccw(c111.979,162.054) 113.479,158.1 113.479,157.05 ccw(c111.979,153.097)
  region net +1V1: 100.832,152.593 cw(c85.838,167.587) 98.844,150.839 99.644,150.439
  region net +1V1: 104.328,151.99 105.128,151.99 ccw(c106.554,151.99) 105.265,151.379 104.217,151.313 ccw(c102.195,151.99)
  region net +1V1: 96.579,141.339 cw(c96.579,143.732) 94.359,142.839 93.609,140.564 94.359,138.339 cw(c96.579,137.446) 96.579,139.839
Bottom Layer:
  drawing of 171 lines, arcs and shapes, not listed

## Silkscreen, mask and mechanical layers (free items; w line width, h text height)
Top Silkscreen Layer:
  text "JTAG" at 143.277,166.326 h3.05 r90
